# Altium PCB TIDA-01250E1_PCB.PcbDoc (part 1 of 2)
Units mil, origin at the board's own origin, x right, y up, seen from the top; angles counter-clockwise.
Board outline 2200 x 3000 mil, 2 copper layers (Top Layer, Bottom Layer), stack 62 mil thick; 78 components, 50 nets, 255 pads, 52 vias.
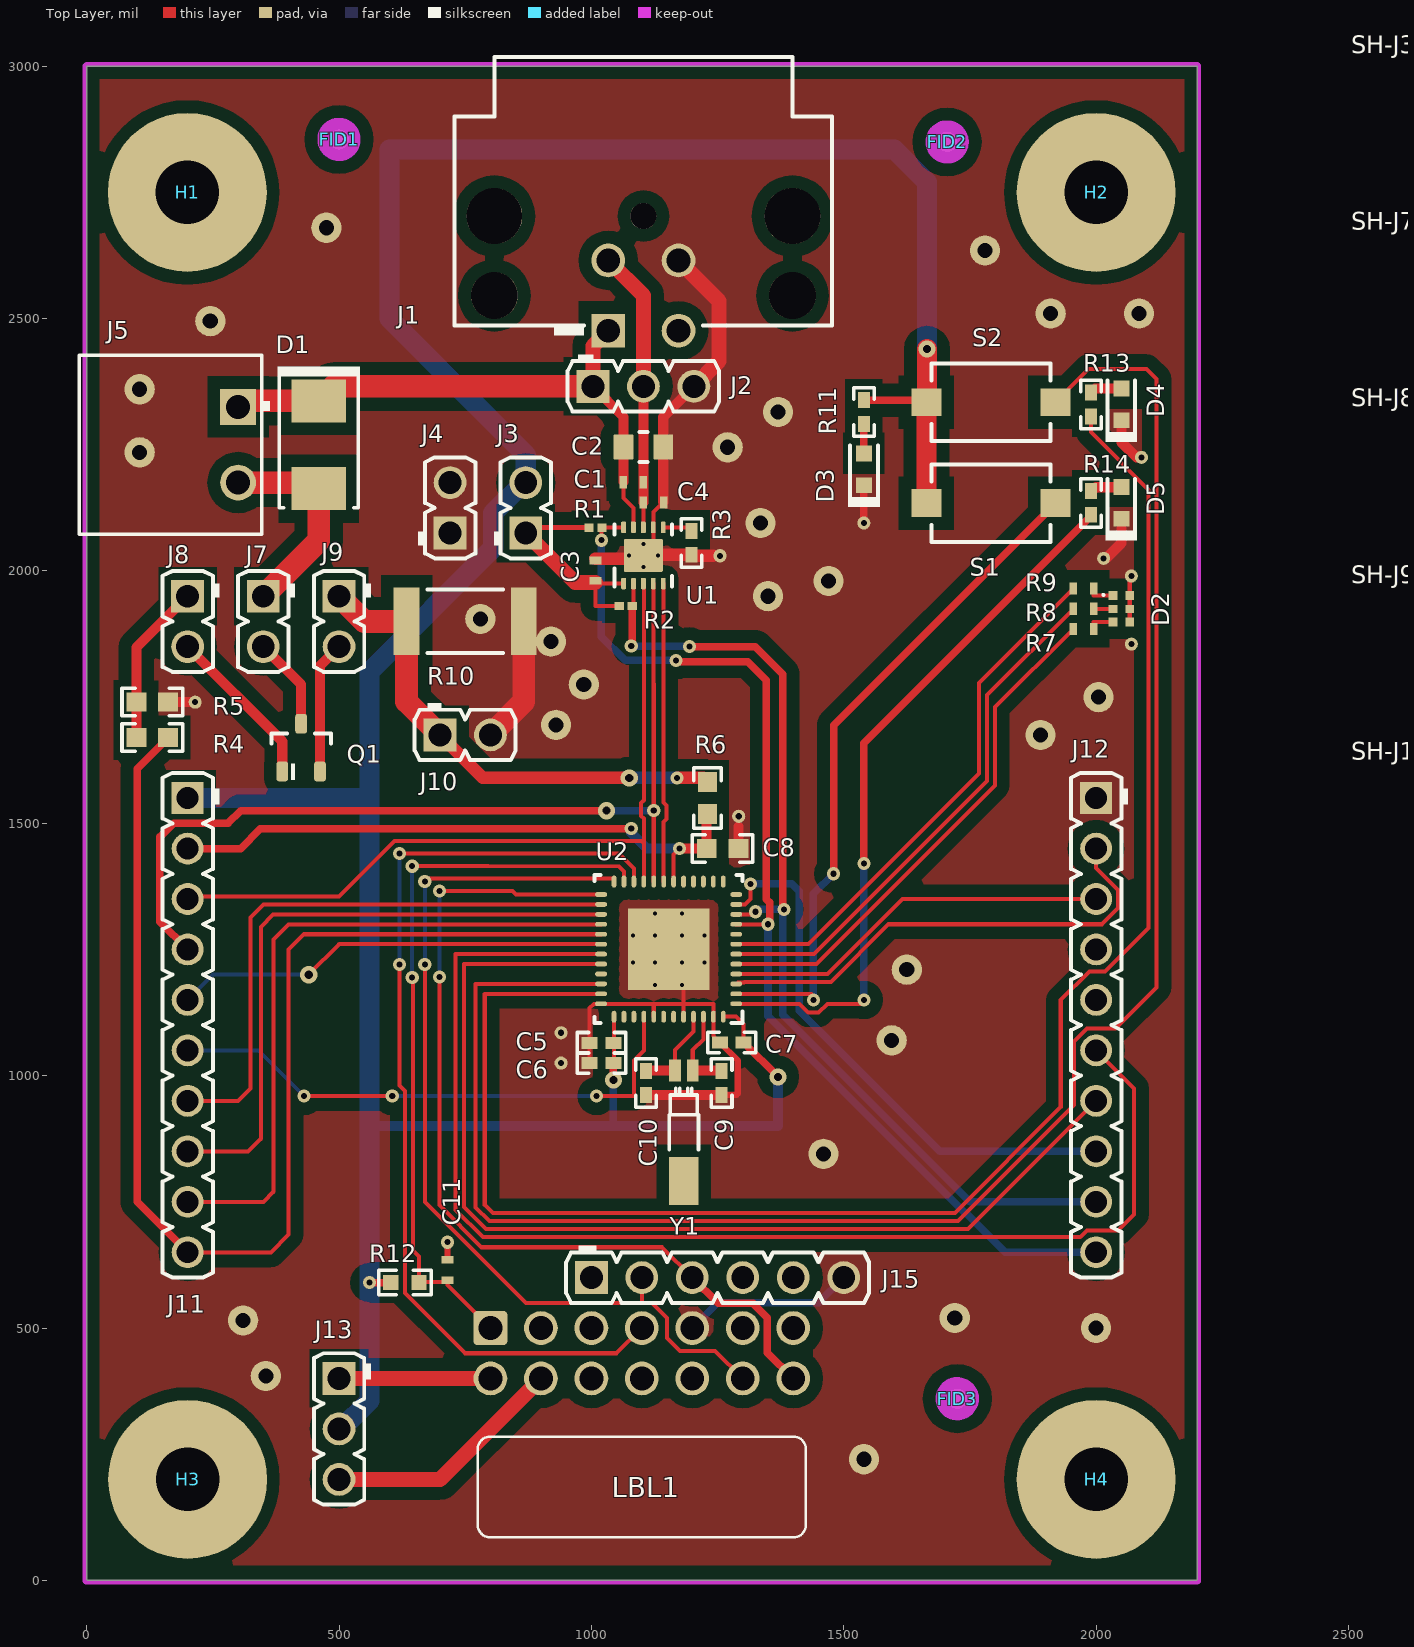
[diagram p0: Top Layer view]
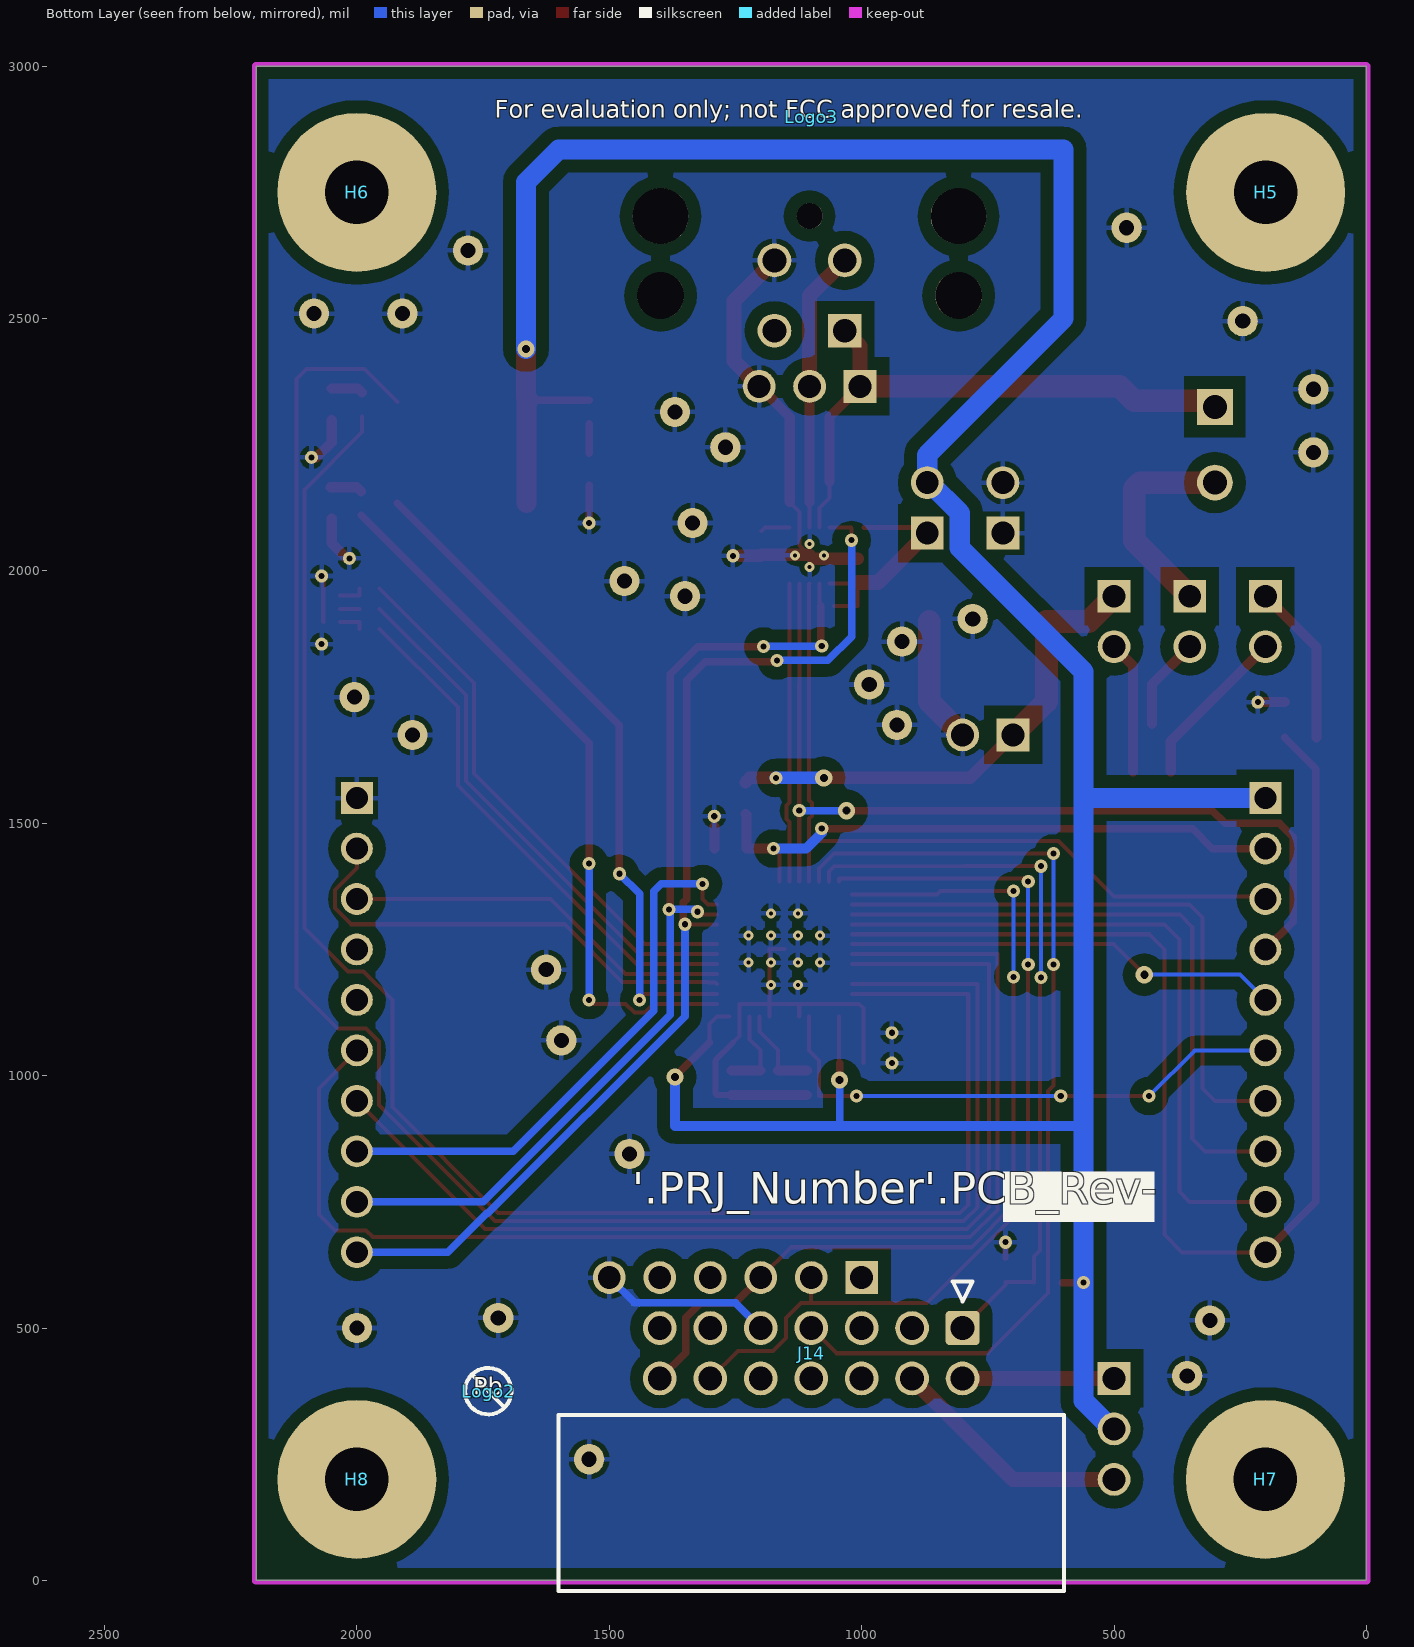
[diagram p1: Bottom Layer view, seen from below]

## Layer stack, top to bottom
Top Solder: solder mask 0.4, Solder Resist, Dk 3.5
Top Layer: signal copper 1.4
Dielectric1: core 59.2, FR-4, Dk 4.8
Bottom Layer: signal copper 1.4
Bottom Solder: solder mask 0.4, Solder Resist, Dk 3.5

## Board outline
0,0 2200,0 2200,3000 0,3000

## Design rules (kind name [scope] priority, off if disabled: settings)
AcuteAngle [All] p1: minimum=4.50000000000000E+0001 checktracksonly=FALSE
AssemblyTestPointUsage [All] p1: valid=2
BoardOutlineClearance BoardOutlineClearance_MountingHoles [OnCopper and InComponentClass('Mounting Holes')] p1: gap=40 ignorepadtopadclearanceinfootprint=FALSE
BoardOutlineClearance BoardOutlineClearance_Poly [OnCopper and IsPoly] p2: gap=25 ignorepadtopadclearanceinfootprint=FALSE
BoardOutlineClearance [OnCopper and Not InComponentClass('Logo') and not InComponentClass('FiducialMark') and not InRegion(1000,500,4000,800) and not InPoly] p3: gap=75 ignorepadtopadclearanceinfootprint=FALSE
Clearance Clearance_FiducialMark [IsKeepOut and InComponentClass('FiducialMark') vs IsPad and InComponentClass('FiducialMark')] p1: gap=0 ignorepadtopadclearanceinfootprint=FALSE
Clearance Clearance_Keepouts [((IsTrack Or IsArc) And Not InPoly) And IsFree and IsKeepOut vs ((IsTrack Or IsArc) And Not InPoly) And IsFree and IsKeepOut] p2: gap=0 ignorepadtopadclearanceinfootprint=FALSE
Clearance Clearance_Poly [InPolygon] p3: gap=25 ignorepadtopadclearanceinfootprint=FALSE except(0: Arc-Hole Track-Hole SMDPad-Hole THPad-Hole Via-Hole Fill-Hole Poly-Hole Region-Hole Text-Hole)
Clearance [All] p4: gap=7.87 ignorepadtopadclearanceinfootprint=FALSE except(0: Arc-Hole Track-Hole SMDPad-Hole THPad-Hole Via-Hole Fill-Hole Poly-Hole Region-Hole Text-Hole)
ComponentClearance ComponentClearance_MountingHoles_FiducialMarks [InComponentClass('Mounting Holes') vs InComponentClass('FiducialMark')] p1: gap=50 collisioncheckmode=3 verticalgap=10 showdistances=FALSE
ComponentClearance ComponentClearance_Shunt [InComponentClass('Header') vs InComponentClass('Shunt')] p2: gap=0 collisioncheckmode=3 verticalgap=0 showdistances=FALSE
ComponentClearance ComponentClearance_Logo [InComponentClass('Logo')] p3: gap=50 collisioncheckmode=3 verticalgap=10 showdistances=FALSE
ComponentClearance ComponentClearance_ScrewToNut [(HasFootprint('NY PMS 440 0025 PH')) vs (HasFootprint('Keystone_1902C'))] p4: gap=5 collisioncheckmode=3 verticalgap=10 showdistances=FALSE
ComponentClearance ComponentClearance_MountingHoles [InComponentClass('Mounting Holes')] p5: gap=100 collisioncheckmode=3 verticalgap=100000 showdistances=FALSE
ComponentClearance ComponentClearance_SmallPassives [HasFootprint('0201*') or HasFootprint('0402*') or HasFootprint('0508') or HasFootprint('0603*') or HasFootprint('0612') or HasFootprint('0805*') or HasFootprint('0815*') or HasFootprint('0830*') or HasFootprint('1206*') or HasFootprint('1210*') or HasFootprint('1808*') or HasFootprint('1812*') or HasFootprint('1825*') or HasFootprint('2010*') or HasFootprint('2220*') or HasFootprint('2225*') or HasFootprint('2512*') or HasFootprint('2728*') or HasFootprint('3518*') vs HasFootprint('0201*') or HasFootprint('0402*') or HasFootprint('0508') or HasFootprint('0603*') or HasFootprint('0612') or HasFootprint('0805*') or HasFootprint('0815*') or HasFootprint('0830*') or HasFootprint('1206*') or HasFootprint('1210*') or HasFootprint('1808*') or HasFootprint('1812*') or HasFootprint('1825*') or HasFootprint('2010*') or HasFootprint('2220*') or HasFootprint('2225*') or HasFootprint('2512*') or HasFootprint('2728*') or HasFootprint('3518*')] p6: gap=14.96 collisioncheckmode=3 verticalgap=10 showdistances=FALSE
ComponentClearance ComponentClearance_THtoSMT [IsThruComponent vs IsSMTComponent] p7: gap=40 collisioncheckmode=3 verticalgap=30 showdistances=FALSE
ComponentClearance ComponentClearance_THtoTH [IsThruComponent vs IsThruComponent] p8: gap=30 collisioncheckmode=3 verticalgap=30 showdistances=FALSE
ComponentClearance [All] p9: gap=30 collisioncheckmode=3 verticalgap=10 showdistances=FALSE
DiffPairsRouting [All] p1: maxlimit=100 minlimit=10 mostfreqgap=10 toplayer_minwidth=15 toplayer_maxwidth=15 toplayer_prefwidth=15 bottomlayer_minwidth=15 bottomlayer_maxwidth=15 bottomlayer_prefwidth=15 maxuncoupledlength=1000
FabricationTestPointUsage TestPointUsage [All] p1: valid=2 allowmultiple=FALSE
FabricationTestpoint Testpoint [All] p1: side=3 testpointundercomponent=TRUE minsize=40 maxsize=100 preferedsize=60 minholesize=0 maxholesize=40 preferedholesize=32 testpointgrid=1 allowsidetop=TRUE allowsidebottom=TRUE usegrid=TRUE gridtolerance=0.01
FanoutControl Fanout_LCC [IsLCC] p1: bgadir=Out bgaviamode=Centered fanoutstyle=Auto fanoutdirection=Alternating viagrid=1 // Fanout_LCC (Default Rule)
FanoutControl Fanout_BGA [IsBGA] p2: bgadir=Out bgaviamode=Centered fanoutstyle=Auto fanoutdirection=Alternating viagrid=1 // Fanout_BGA (Default Rule)
FanoutControl Fanout_Default [All] p4: bgadir=Out bgaviamode=Centered fanoutstyle=Auto fanoutdirection=Alternating viagrid=1 // Fanout_Default (Default Rule)
FanoutControl Fanout_Small [(CompPinCount < 5)] p5: bgadir=Out bgaviamode=Centered fanoutstyle=Auto fanoutdirection=OutThenIn viagrid=1 // Fanout_Small (Default Rule)
HoleSize [All] p1: absolutevalues=TRUE maxlimit=251 minlimit=7.87 maxpercent=80.000 minpercent=20.000
MinimumAnnularRing MinimumAnnularRing_ThermalPadVias [IsVia and InAnyComponent] p1: minimumring=5.91
MinimumAnnularRing [All] p2: minimumring=6.9
MinimumSolderMaskSliver MinimumSolderMaskSliver_Logo [InComponentClass('Logo') vs InComponentClass('Logo')] p1: minsoldermaskwidth=0.7
MinimumSolderMaskSliver [All] p2: minsoldermaskwidth=3.94
PlaneConnect [All] p1: planeconnectstyle=Relief reliefexpansion=10 reliefentries=4 reliefconductorwidth=10 reliefairgap=10
PolygonConnect PolygonConnect_1 [All vs IsNamedPolygon('TOP_LAYER_GND_P002')] p1: connectstyle=Direct reliefconductorwidth=10 reliefentries=4 polygonreliefangle="90 Angle" airgapwidth=10
PolygonConnect [All] p2: connectstyle=Relief reliefconductorwidth=10 reliefentries=4 polygonreliefangle="90 Angle" airgapwidth=10
RoutingVias ThermalPadVias [IsVia and InAnyComponent] p1: holewidth=7.87 width=19.68 viastyle="Through Hole" minholewidth=7.87 minwidth=19.68 maxholewidth=12.99 maxwidth=23.62
RoutingVias [All] p2: holewidth=16 width=34 viastyle="Through Hole" minholewidth=7.87 minwidth=26 maxholewidth=40 maxwidth=65
SilkToBoardRegionClearance [Not ((IsComment or IsDesignator) And (Hide <> 'False')) and not InRegion(1000,500,4000,800)] p1:
SilkToSilkClearance SilkToSilkClearance_Pb-FreeLogo [(HasFootprint('Pb-Free_Overlay_Medium') OR HasFootprint('Pb-Free_Overlay_Small')) vs (HasFootprint('Pb-Free_Overlay_Medium') OR HasFootprint('Pb-Free_Overlay_Small'))] p1: silktosilkclearance=0
SilkToSilkClearance [All] p2: silktosilkclearance=4
SilkToSolderMaskClearance SilkToComponentPadClearance [(IsPad or IsFill or IsRegion) and InAnycomponent] p1: minsilkscreentomaskgap=5 clearancetoexposedcopper=TRUE
SilkToSolderMaskClearance "Silk to Solder Mask Opening" [All] p2: minsilkscreentomaskgap=4 clearancetoexposedcopper=FALSE
SolderMaskExpansion [All] p1: expansion=1.97
Width [All] p1: maxlimit=100 minlimit=6 preferedwidth=10 checkconnectedcopper=TRUE
15 further rules are at their usual default settings.

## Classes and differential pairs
component class TIDA-01250E1_Schematic: C1 C2 C3 C4 C5 C6 C7 C8 C9 C10 C11 D1 D2 D3 D4 D5 J1 J2 J3 J4 J5 J7 J8 J9 J10 J11 J12 J13 J14 J15 Q1 R1 R2 R3 R4 R5 R6 R7 R8 R9 R10 R11 R12 R13 R14 S1 S2 SH-J3 SH-J7 SH-J8 SH-J9 SH-J13 U1 U2 Y1
component class Header: J2 J3 J4 J7 J8 J9 J10 J11 J12 J13 J15
component class "Mounting Holes": H1 H2 H3 H4
component class TIDA-01250E1_EVM_Hardware: FID1 FID2 FID3 H1 H2 H3 H4 H5 H6 H7 H8 LBL1 Logo2 Logo3 ZZ1 ZZ2 ZZ3 ZZ4 ZZ5 ZZ6 ZZ7 ZZ8 ZZ9
component class FiducialMark: FID1 FID2 FID3
component class AssemblyNote: ZZ1 ZZ2 ZZ3 ZZ4 ZZ5 ZZ6 ZZ7 ZZ8 ZZ9
component class Label: LBL1

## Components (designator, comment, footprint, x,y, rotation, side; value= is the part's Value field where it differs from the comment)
C1 "GRM1555C1H151JA01D" 0402S 1083.15,2175.67 r0 top value=150pF
C2 "CGA4J3X7S2A105K125AB" 0805_HV1 1103.15,2245.67 r0 top value=1uF
C3 "GRM155R61A105KE15D" 0402S 1008.15,2000.67 r90 top value=1uF
C4 "GRM1555C1H151JA01D" 0402S 1123.15,2135.67 r0 top value=150pF
C5 "GRM155R71C104JA88D" 0402 1020,1065 r180 top value=0.1uF
C6 "GRM155R61A105KE15D" 0402 1020,1025 r180 top value=1uF
C7 "GRM155R71C104JA88D" 0402 1278.15,1065.67 r180 top value=0.1uF
C8 "GRM1885C1H101JA01D" 0603 1260,1450 r0 top value=100pF
C9 "GRM1555C1H100RA01D" 0402 1258.15,985.67 r270 top value=10pF
C10 "GRM1555C1H100RA01D" 0402 1108.15,985.67 r270 top value=10pF
C11 "885012205061" 0402S 715,615 r90 top value=1000pF
D1 "MURS160-13-F" SMB 460,2250 r270 top value=600V
D2 "SMLP36RGB2W3" PicoLED_RGB_150x100 2050,1925 r0 top value=Rgb
D3 "150060VS75000" WL-SMCW_GREEN 1540,2201.4 r90 top value=Green
D4 "150060VS75000" WL-SMCW_GREEN 2050,2330 r90 top value=Green
D5 "150060VS75000" WL-SMCW_GREEN 2050,2135 r90 top value=Green
FID1 "Fiducial" Fiducial10-20 500,2855 r0 top
FID2 "Fiducial" Fiducial10-20 1705,2850 r0 top
FID3 "Fiducial" Fiducial10-20 1725,360 r0 top
H1 "NY PMS 440 0025 PH" "NY PMS 440 0025 PH" 199.47,2750 r0 top locked
H2 "NY PMS 440 0025 PH" "NY PMS 440 0025 PH" 2000,2750 r0 top locked
H3 "NY PMS 440 0025 PH" "NY PMS 440 0025 PH" 200,200 r0 top locked
H4 "NY PMS 440 0025 PH" "NY PMS 440 0025 PH" 2000,200 r0 top locked
H5 "1902C" Keystone_1902C 199.47,2750 r180 bottom locked
H6 "1902C" Keystone_1902C 2000,2750 r180 bottom locked
H7 "1902C" Keystone_1902C 200,200 r180 bottom locked
H8 "1902C" Keystone_1902C 2000,200 r180 bottom locked
J1 "PartNumber" Conec_43-01205 1103.15,2545.67 r90 top
J2 "61300311121" WURTH_61300311121 1103.16,2365.68 r0 top
J3 "61300211121" WURTH_61300211121 870,2125 r90 top
J4 "61300211121" WURTH_61300211121 720,2125 r90 top
J5 "1803277" PhoenixContact_1803277 300,2250 r270 top
J7 "61300211121" WURTH_61300211121 350,1900 r270 top
J8 "61300211121" WURTH_61300211121 200,1900 r270 top
J9 "61300211121" WURTH_61300211121 500,1900 r270 top
J10 "61300211121" WURTH_61300211121 750,1675 r0 top
J11 "61301011121" Wurth_61301011121 200,1100 r270 top
J12 "61301011121" Wurth_61301011121 2000,1100 r270 top
J13 "61300311121" WURTH_61300311121 500,300 r270 top
J14 "612 014 217 21" WURTH_612_014_217_21_Correct 1100,450 r270 bottom
J15 "61300611121" WURTH_61300611121 1250,600 r0 top
LBL1 "THT-14-423-10" Label_650x200 1100,185 r0 top
Logo2 "Pb-Free Symbol" Pb-Free_Overlay_Small 1740,375 r180 bottom
Logo3 "FCC disclaimer" FCC_disclaimer 1100,2900 r180 bottom
Q1 "DMN61D8L-7" SOT-23 425,1650 r90 top value=60V
R1 "CRCW020110K0FKED" 0201 1008.15,2085.67 r180 top value=10.0k
R2 "CRCW020110K0FKED" 0201 1068.15,1930.67 r180 top value=10.0k
R3 "CRCW04020000Z0ED" 0402 1198.15,2055.67 r270 top value=0
R4 "CRCW06030000Z0EA" 0603 130,1670 r180 top value=0
R5 "CRCW0603100KFKEA" 0603 130,1740 r180 top value=100k
R6 "CRCW06031K00FKEA" 0603 1230,1550 r90 top value=1.00k
R7 "CRCW0402140RFKED" 0402S 1975,1885 r0 top value=140
R8 "CRCW0402140RFKED" 0402S 1975,1925 r0 top value=140
R9 "CRCW0402499RFKED" 0402S 1975,1965 r0 top value=499
R10 "CRCW25121R00FNEG" 2512 750,1900 r180 top value=1.00
R11 "CRCW040268R1FKED" 0402 1540,2315 r270 top value=68.1
R12 "CRCW060347K5FKEA" 0603_HV 630.41,590 r180 top value=47.5k
R13 "CRCW040268R1FKED" 0402 1990,2330 r90 top value=68.1
R14 "CRCW040268R1FKED" 0402 1990,2135 r90 top value=68.1
S1 "434121025816" SW_434121025816 1791.85,2134.33 r180 top
S2 "434121025816" SW_434121025816 1791.85,2334.33 r180 top
SH-J3 "60900213421" Wurth_60900213421 2550,2900 r90 top
SH-J7 "60900213421" Wurth_60900213421 2550,2550 r90 top
SH-J8 "60900213421" Wurth_60900213421 2550,2200 r90 top
SH-J9 "60900213421" Wurth_60900213421 2550,1850 r90 top
SH-J13 "60900213421" Wurth_60900213421 2550,1500 r90 top
U1 "TIOL111" TIOL111 1103.15,2030.67 r90 top
U2 "MSP430FR5969IRGZR" RGZ0048B 1153.15,1250.67 r180 top
Y1 "MS3V-T1R 32.768KHZ 7.0 PF" XTAL_MS3V-T1R 1183.15,900.67 r270 top
ZZ1 "This Assembly Note is for PCB labels only" AssemblyNoteLabel 185,3938 r0 top
ZZ2 "This Assembly Note will show in the PcbDoc and associated outputs" AssemblyNote 185,3829.11 r0 top
ZZ3 "This Assembly Note will show in the PcbDoc and associated outputs" AssemblyNote 185,3740.56 r0 top
ZZ4 "This Assembly Note will show in the PcbDoc and associated outputs" AssemblyNote 185,3652 r0 top
ZZ5 "This Assembly Note will show in the PcbDoc and associated outputs" AssemblyNote 2900,2950 r0 top
ZZ6 "This Assembly Note will show in the PcbDoc and associated outputs" AssemblyNote 2900,2600 r0 top
ZZ7 "This Assembly Note will show in the PcbDoc and associated outputs" AssemblyNote 2900,2250 r0 top
ZZ8 "This Assembly Note will show in the PcbDoc and associated outputs" AssemblyNote 2900,1900 r0 top
ZZ9 "This Assembly Note will show in the PcbDoc and associated outputs" AssemblyNote 2900,1550 r0 top

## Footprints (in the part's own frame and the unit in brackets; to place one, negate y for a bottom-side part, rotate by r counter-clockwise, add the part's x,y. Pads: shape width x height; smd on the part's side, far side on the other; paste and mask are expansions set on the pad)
0201 [mm] "Data from Kemet datasheet CC101_COM dated 7/28/11"
  rect 0.46x0.42 smd mask+0.048: 1(-0.33,0) 2(0.33,0)
  body extent -0.31,-0.16 0.31,0.16, height 0.26
0402 [mm] "0402 from SM-752 data"
  rect 0.8x0.6 smd: 1(-0.6,0) 2(0.6,0)
  silkscreen extent -1.22,-0.52 1.22,0.52, body extent -0.55,-0.3 0.55,0.3, height 0.6
0402S [mil] "Based on C0402S footprint from PADS legacy"
  rect 15x24 smd: 1(-20,0) 2(20,0)
  body extent -22,-12 22,12, height 24
0603 [mm] "0603 from SM-752 data"
  rect 1x0.95 smd: 1(-0.8,0) 2(0.8,0)
  silkscreen extent -1.52,-0.69 1.52,0.69, body extent -0.87,-0.47 0.87,0.47, height 1
0603_HV [mil] "Ernesto recommended land pattern.  26 mil between pads."
  rect 30x30 smd: 1(-28,0) 2(28,0)
  silkscreen extent -52,-24 52,24, body extent -34,-19 34,19, height 39
0805_HV1 [mm] "Custom footprint based on analyzing multiple manufacturer recommendations"
  rrect10% 1x1.25 smd: 1(-1,0) 2(1,0)
  silkscreen extent -0.2,-0.75 0.2,0.75, body extent -1.1,-0.72 1.1,0.73, height 1.45
2512 [mm] "Chip Resistor, Body 6.3x3.2mm, IPC Medium Density"
  rect 1.3x3.4 smd: 1(-2.95,0) 2(2.95,0)
  silkscreen extent -1.9,-1.6 1.9,1.6, body extent -3.22,-1.67 3.22,1.67, height 0.71
AssemblyNote [mil] "Assembly Note"
AssemblyNoteLabel [mil] "Assembly Note for PCB Labels"
Conec_43-01205 [mm] "M12 Socket, Backmounting, 4Pos, R/A, TH"
  rect 1.7x1.7 hole 1.2: 1(-1.768,1.768)
  round 1.7 hole 1.2: 2(-1.768,-1.768) 3(1.768,-1.768) 4(1.768,1.768)
  round 2.35 hole 2.35 unplated mask+0: 5(0,7.5) 6(0,-7.5)
  round 2.8 hole 2.8 unplated mask+0: 7(4,-7.5) 8(4,7.5)
  round 1.3 hole 1.3 unplated mask+0: 9(4,0)
  silkscreen extent -2,-9.5 12,9.5, body extent -2.15,-9.5 25,9.5, height 17
FCC_disclaimer [mil]
Fiducial10-20 [mm]
  round 1 smd mask+0.5: 1(0,0)
  Top Layer keep-out circle w1.178: c0,0 r0.5
Keystone_1902C [mil] "Hex Standoff, 4-40 threaded, nylon"
  round 1 on Mech4: 0(0,0)
  body extent -145,-126 146,126, height 501
Label_650x200 [mil] "Thermal Transfer Label"
  round 1 on Mech13: 0(0,0)
  silkscreen extent -325,-100 325,100, body extent -325,-100 325,100, height 1
"NY PMS 440 0025 PH" [mm] "4-40 nylon screw and mounting hole"
  round 8 hole 3.2: 1(0,0)
  body extent -3.3,-3.3 3.3,3.3, height 2.69
Pb-Free_Overlay_Small [mil]
  silkscreen extent -46,-46 46,46
PhoenixContact_1803277 [mm] "Phoenix Contact"
  rect 1.8x1.8 hole 1.2: 1(-1.905,0)
  round 1.8 hole 1.2: 2(1.905,0)
  silkscreen extent -4.5,-8 4.51,1.6, body extent -4.5,-8 4.51,1.3, height 7.26
PicoLED_RGB_150x100 [mm] "SMD, 6-Leads, Body 1.5x1mm"
  rect 0.45x0.45 smd: 1(-0.425,0.675) 3(-0.425,-0.675) 4(0.425,-0.675) 6(0.425,0.675)
  rect 0.45x0.4 smd: 2(-0.425,0) 5(0.425,0)
  silkscreen extent -0.95,0.65 -0.85,0.75, body extent -0.5,-0.75 0.5,0.75, height 0.25
RGZ0048B [mm] "QFN, 48-Leads, Body 7x7mm, Pitch 0.5mm, Thermal Pad 5.15x5.15mm, TI Recommended"
  oval 0.6x0.24 smd: 1(-3.4,2.75) 2(-3.4,2.25) 3(-3.4,1.75) 4(-3.4,1.25) 5(-3.4,0.75) 6(-3.4,0.25) 7(-3.4,-0.25) 8(-3.4,-0.75) 9(-3.4,-1.25) 10(-3.4,-1.75) 11(-3.4,-2.25) 12(-3.4,-2.75) 25(3.4,-2.75) 26(3.4,-2.25) 27(3.4,-1.75) 28(3.4,-1.25) 29(3.4,-0.75) 30(3.4,-0.25) 31(3.4,0.25) 32(3.4,0.75) 33(3.4,1.25) 34(3.4,1.75) 35(3.4,2.25) 36(3.4,2.75)
  oval 0.24x0.6 smd: 13(-2.75,-3.4) 14(-2.25,-3.4) 15(-1.75,-3.4) 16(-1.25,-3.4) 17(-0.75,-3.4) 18(-0.25,-3.4) 19(0.25,-3.4) 20(0.75,-3.4) 21(1.25,-3.4) 22(1.75,-3.4) 23(2.25,-3.4) 24(2.75,-3.4) 37(2.75,3.4) 38(2.25,3.4) 39(1.75,3.4) 40(1.25,3.4) 41(0.75,3.4) 42(0.25,3.4) 43(-0.25,3.4) 44(-0.75,3.4) 45(-1.25,3.4) 46(-1.75,3.4) 47(-2.25,3.4) 48(-2.75,3.4)
  rect 4.1x4.1 smd paste-2.575: 49(0,0)
  silkscreen extent -3.72,-3.72 3.72,3.72, body extent -3.57,-3.58 3.58,3.57, height 1.01
SMB [mil] "Molded Diode, 2-Leads, Body 5.4x3.6mm, IPC Medium Density, based on OnSemi component dimensions"
  rect 85x107.99 smd: 1(-87.01,0) 2(87.01,0)
  silkscreen extent -155,-82 125,82, body extent -106,-71 106,71, height 91
SOT-23 [mm] "SOT23, 3-Leads, Body 2.9x1.3mm, Pitch 0.95mm, Lead Span 2.5mm, IPC Medium Density"
  rrect50% 1x0.6 smd: 1(-1.2,0.95) 2(-1.2,-0.95) 3(1.2,0)
  silkscreen extent -1.62,-1.5 0.7,1.5, body extent -1.16,-1.45 1.21,1.45, height 1
SW_434121025816 [mm] "SMD, 2-Leads, Body 6x3.9mm, Pitch 6.5mm"
  rect 1.5x1.4 smd: 1(-3.25,0) 2(3.25,0)
  silkscreen extent -3,-1.95 3,1.95, body extent -3.65,-1.95 3.65,1.95, height 2.5
TIOL111 [mm] "SON, 10-Leads, Body 2.5x3mm, Pitch 0.5mm, Thermal Pad 1.95x1.65mm"
  rrect40% 0.575x0.24 smd: 1(-1.412,1) 2(-1.412,0.5) 3(-1.412,0) 4(-1.412,-0.5) 5(-1.412,-1) 6(1.412,-1) 7(1.412,-0.5) 8(1.412,0) 9(1.412,0.5) 10(1.412,1)
  rrect6% 1.65x1.95 smd paste-2: 11(0,0)
  silkscreen extent -1.55,-1.45 1.55,1.45, body extent -1.55,-1.3 1.55,1.3, height 1.02
WL-SMCW_GREEN [mm] "WURTH"
  rect 0.8x0.8 smd: 1(-0.8,0) 2(0.8,0)
  silkscreen extent -1.9,-0.8 1.2,0.8, body extent -0.85,-0.45 0.85,0.45, height 0.8
WURTH_612_014_217_21_Correct [mm] "Header, 2.54 mm, 7x2, R/A, TH"
  rrect20% 1.7x1.7 hole 1.2: 1(-1.27,7.62)
  round 1.7 hole 1.2: 2(1.27,7.62) 3(-1.27,5.08) 4(1.27,5.08) 5(-1.27,2.54) 6(1.27,2.54) 7(-1.27,0) 8(1.27,0) 9(-1.27,-2.54) 10(1.27,-2.54) 11(-1.27,-5.08) 12(1.27,-5.08) 13(-1.27,-7.62) 14(1.27,-7.62)
  silkscreen extent -3.6,-12.72 11.96,12.72, body extent -1.59,-12.72 11.96,12.72, height 9.1
Wurth_60900213421 [mil] "Shunt, 2.54mm, Black"
  round 1 on Mech3: 0(0,0)
  body extent -98,-48 98,48, height 236
WURTH_61300211121 [mm] "Header, 2.54mm, 2x1, TH"
  rect 1.65x1.65 hole 1.15: 1(-1.27,0)
  round 1.65 hole 1.15: 2(1.27,0)
  silkscreen extent -2.54,-1.27 2.54,1.6, body extent -2.54,-1.27 2.54,1.27, height 8.54
WURTH_61300311121 [mm] "Header, 2.54mm, 3x1, TH"
  rect 1.65x1.65 hole 1.15: 1(-2.54,0)
  round 1.65 hole 1.15: 2(0,0) 3(2.54,0)
  silkscreen extent -3.81,-1.27 3.81,1.6, body extent -3.81,-1.27 3.81,1.27, height 8.54
WURTH_61300611121 [mm] "Header, 2.54mm, 6x1, TH"
  rect 1.65x1.65 hole 1.15: 1(-6.35,0)
  round 1.65 hole 1.15: 2(-3.81,0) 3(-1.27,0) 4(1.27,0) 5(3.81,0) 6(6.35,0)
  silkscreen extent -7.62,-1.27 7.62,1.6, body extent -7.62,-1.27 7.62,1.27, height 8.54
Wurth_61301011121 [mm] "Header, 2.54mm, 10x1, TH"
  rect 1.6x1.6 hole 1.1: 1(-11.43,0)
  round 1.6 hole 1.1: 2(-8.89,0) 3(-6.35,0) 4(-3.81,0) 5(-1.27,0) 6(1.27,0) 7(3.81,0) 8(6.35,0) 9(8.89,0) 10(11.43,0)
  silkscreen extent -12.7,-1.27 12.7,1.6, body extent -12.7,-1.27 12.7,1.27, height 8.54
XTAL_MS3V-T1R [mm] "Micro Crystal Switzerland recommended land pattern"
  rect 1.1x0.6 smd: 1(-2.775,0.45) 2(-2.775,-0.45)
  rect 2.4x1.5 smd: 3(2.775,0)
  silkscreen extent -1.9,-0.74 1.2,0.74, body extent -3.05,-0.74 3.65,0.74, height 1.42

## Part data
C1 C4: library part CMP-0006421-1, "CAP, CERM, 150 pF, 50 V, +/- 5%, C0G/NP0, 0402", Cap_Case=0402, Manufacturer=MuRata, Supplier Part Number 1=490-3229-1-ND, TempCo=C0G/NP0, Tolerance_%=5%, Value1=Unknown, Value2=50V, ValueDisplayed=150pF
C2: library part CMP-0007980-2, "CAP, CERM, 1 uF, 100 V, +/- 10%, X7S, AEC-Q200 Grade 1, 0805", Cap_Case=0805, Manufacturer=TDK, Supplier Part Number 1=445-6974-1-ND, TempCo=X7S, Tolerance_%=10%, Value1="0.008255 ohm", Value2=100V, ValueDisplayed=1uF
C3 C6: library part CMP-0006563-2, "CAP, CERM, 1 uF, 10 V, +/- 10%, X5R, 0402", Cap_Case=0402, Manufacturer=MuRata, Supplier Part Number 1=490-3890-1-ND, TempCo=X5R, Tolerance_%=10%, Value1=Unknown, Value2=10V, ValueDisplayed=1uF
C5 C7: library part CMP-0006640-2, "CAP, CERM, 0.1 uF, 16 V, +/- 5%, X7R, 0402", Cap_Case=0402, Manufacturer=MuRata, Supplier Part Number 1=490-6327-1-ND, TempCo=X7R, Tolerance_%=5%, Value1=Unknown, Value2=16V, ValueDisplayed=0.1uF
C8: library part CMP-0007171-1, "CAP, CERM, 100 pF, 50 V, +/- 5%, C0G/NP0, 0603", Cap_Case=0603, Manufacturer=MuRata, Supplier Part Number 1=490-1427-1-ND, TempCo=C0G/NP0, Tolerance_%=5%, Value1=Unknown, Value2=50V, ValueDisplayed=100pF
C9 C10: library part CMP-0006409-1, "CAP, CERM, 10 pF, 50 V, +/- 4%, C0G/NP0, 0402", Cap_Case=0402, Manufacturer=MuRata, Supplier Part Number 1=490-11374-1-ND, TempCo=C0G/NP0, Tolerance_%=4%, Value1=Unknown, Value2=50V, ValueDisplayed=10pF
C11: library part CMP-0006231-2, "CAP, CERM, 1000 pF, 50 V, +/- 10%, X7R, 0402", Cap_Case=0402, Manufacturer="Wurth Elektronik", Supplier Part Number 1=732-7556-1-ND, TempCo=X7R, Tolerance_%=10%, Value1=Unknown, Value2=50V, ValueDisplayed=1000pF
D1: library part CMP-0029028-1, "Diode, Ultrafast, 600 V, 1 A, SMB", Manufacturer="Diodes Inc.", Supplier Part Number 1=MURS160-FDICT-ND, Value1=1A, Value2=1.25V
D2: library part CMP-0002932-2, "LED, Rgb, SMD", Color=RGB, Manufacturer=Rohm, Supplier Part Number 1=846-1097-1-ND, Value1=W, Value2=3.1V
D3 D4 D5: library part CMP-0002894-1, "LED, Green, SMD", Color=green, Manufacturer="Wurth Elektronik", Supplier Part Number 1=732-4980-1-ND, Value1=W, Value2=2V
FID1 FID2 FID3: "Fiducial mark.  There is nothing to buy or mount.", Manufacturer=N/A
H1 H2 H3 H4: library part CMP-0003617-1, "Machine Screw, Round, #4-40 x 1/4, Nylon, Philips panhead", Manufacturer="B&F Fastener Supply", Supplier Part Number 1=H542-ND
H5 H6 H7 H8: library part CMP-0003610-1, "Standoff, Hex, 0.5\"L #4-40 Nylon", Manufacturer=Keystone, Supplier Part Number 1=36-1902C-ND
J1: library part 43-01205, "M12 Socket, Backmounting, 4Pos, Gold, R/A, TH"
J2 J13: library part CMP-0054796-1, "Header, 2.54 mm, 3x1, Gold, TH", Manufacturer="Wurth Elektronik", Supplier Part Number 1=732-5316-ND
J3 J4 J7 J8 J9 J10: library part CMP-0054794-1, "Header, 2.54 mm, 2x1, Gold, TH", Manufacturer="Wurth Elektronik", Supplier Part Number 1=732-5315-ND
J5: library part CMP-0055494-1, "Terminal Block, 2x1, 3.81mm, R/A, TH", Manufacturer="Phoenix Contact", Supplier Part Number 1=277-1206-ND
J11 J12: library part CMP-0054804-1, "Header, 2.54mm, 10x1, Gold, TH", Color=Black, Manufacturer="Wurth Elektronik", Supplier Part Number 1=732-2670-ND
J14: library part CMP-0054781-1, "Header (Shrouded), 2.54 mm, 7x2, Gold, R/A, TH", Manufacturer="Wurth Elektronik", Supplier Part Number 1=732-5407-ND
J15: library part CMP-0054801-1, "Header, 2.54 mm, 6x1, Gold, TH", Manufacturer="Wurth Elektronik", Supplier Part Number 1=732-5319-ND
LBL1: library part CMP-0003625-1, "Thermal Transfer Printable Labels, 0.650\" W x 0.200\" H - 10,000 per roll", Manufacturer=Brady, Supplier Part Number 1=97C5133
Logo2: library part Pb-Free
Logo3: library part FCC_disclaimer, "FCC_disclaimer"
Q1: library part CMP-0000830-1, "MOSFET, N-CH, 60 V, 0.47 A, AEC-Q101, SOT-23", Alternate Manufacturer=None, Manufacturer="Diodes Inc.", Supplier Part Number 1=DMN61D8L-7DICT-ND, Value2="0.74 nC"
R1 R2: library part CMP-0027262-1, "RES, 10.0 k, 1%, 0.05 W, 0201", Manufacturer=Vishay-Dale, Power_W=50mW, Supplier Part Number 1=541-10.0KAABCT-ND, TempCo="100 ppm/C", Tolerance_%=1%, Value2=0.05W, Value_Code=10k0, ValueDisplayed=10.0k
R3: library part CMP-0026822-1, "RES, 0, 5%, 0.063 W, 0402", Manufacturer=Vishay-Dale, Power_W=63mW, Supplier Part Number 1=541-0.0JCT-ND, TempCo="200 ppm/C", Tolerance_%=5%, Value2=0.063W, Value_Code=0000, ValueDisplayed=0
R4: library part CMP-0025697-1, "RES, 0, 5%, 0.1 W, 0603", Manufacturer=Vishay-Dale, Power_W=100mW, Supplier Part Number 1=541-0.0GCT-ND, TempCo="200 ppm/C", Tolerance_%=5%, Value2=0.1W, Value_Code=0000, ValueDisplayed=0
R5: library part CMP-0021990-1, "RES, 100 k, 1%, 0.1 W, 0603", Manufacturer=Vishay-Dale, Power_W=100mW, Supplier Part Number 1=541-100KHCT-ND, TempCo="100 ppm/C", Tolerance_%=1%, Value2=0.1W, Value_Code=100k
R6: library part CMP-0022109-2, "RES, 1.00 k, 1%, 0.1 W, 0603", Manufacturer=Vishay-Dale, Power_W=100mW, Supplier Part Number 1=541-1.00KHCT-ND, TempCo="100 ppm/C", Tolerance_%=1%, Value2=0.1W, Value_Code=1k00, ValueDisplayed=1.00k
R7 R8: library part CMP-0026010-2, "RES, 140, 1%, 0.063 W, 0402", Manufacturer=Vishay-Dale, Power_W=63mW, Supplier Part Number 1=541-140LCT-ND, TempCo="100 ppm/C", Tolerance_%=1%, Value2=0.063W, Value_Code=140R, ValueDisplayed=140
R9: library part CMP-0026402-1, "RES, 499, 1%, 0.063 W, 0402", Manufacturer=Vishay-Dale, Power_W=63mW, Supplier Part Number 1=541-499LCT-ND, TempCo="100 ppm/C", Tolerance_%=1%, Value2=0.063W, Value_Code=499R, ValueDisplayed=499
R10: library part CMP-0015520-1, "RES, 1.00, 1%, 1 W, AEC-Q200 Grade 0, 2512", Manufacturer=Vishay-Dale, Power_W=1W, Supplier Part Number 1=541-1.00AFCT-ND, TempCo="200 ppm/C", Tolerance_%=1%, Value_Code=1R00, ValueDisplayed=1.00
R11 R13 R14: library part CMP-0026507-1, "RES, 68.1, 1%, 0.063 W, 0402", Manufacturer=Vishay-Dale, Power_W=63mW, Supplier Part Number 1=541-68.1LCT-ND, TempCo="100 ppm/C", Tolerance_%=1%, Value2=0.063W, Value_Code=68R1, ValueDisplayed=68.1
R12: library part CMP-0022439-1, "RES, 47.5 k, 1%, 0.1 W, 0603", Manufacturer=Vishay-Dale, Power_W=100mW, Supplier Part Number 1=541-47.5KHCT-ND, TempCo="100 ppm/C", Tolerance_%=1%, Value2=0.1W, Value_Code=47k5, ValueDisplayed=47.5k
S1 S2: library part CMP-0002196-1, "Switch, Tactile, SPST, 12 V, SMD", CurrentRating_mA=50A, Manufacturer="Wurth Elektronik", Supplier Part Number 1=31T8978
SH-J3 SH-J7 SH-J8 SH-J9 SH-J13: library part CMP-0003761-1, "Shunt, 2.54mm, Gold, Black", Manufacturer="Wurth Elektronik", Supplier Part Number 1=732-2678-ND
U1: library part CMP-0014126-1, "IO-Link Device Transceiver with Integrated Surge Protection, TIOL111 (WSON-10)", Alternate Manufacturer="Texas Instruments"
U2: library part CMP-0066503-1, "MSP430FR5969 16 MHz Ultra-Low-Power Microcontroller featuring 64 KB FRAM, 2 KB SRAM, 40 IO, RGZ0048B (VQFN-48)", Alternate Manufacturer="Texas Instruments", Alternate PartNumber=MSP430FR5969IRGZT
Y1: library part CMP-0004695-1, "Crystal, 32.768 KHz, 7pF, SMD", Frequency_Fixed=32.768kHz, Manufacturer="Micro Crystal AG"
ZZ1: library part AssemblyNoteLabel
ZZ2 ZZ3 ZZ4 ZZ5 ZZ6 ZZ7 ZZ8 ZZ9: library part AssemblyNote

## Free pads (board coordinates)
  round 26 hole 12: 2(2090,2225) 3(2015,2025) 4(2070,1990) 5(215,1740) 5(1292.01,1513.94) 6(940,1025) 6(940,1085) 6(1540,2095) 6(2070,1855)
  round 60 hole 30: 7(1780,2635) 8(1910,2510) 9(2085,2510) 10(1370,2315) 11(1270,2245) 12(1335,2095) 13(1470,1980) 14(1350,1950) 15(920,1860) 16(985,1775) 17(930,1695) 18(780,1905) 19(475,2680) 20(245,2495) 21(105,2360) 22(105,2235) 23(310,515) 24(355,405) 26(1540,240) 27(1720,520) 28(2000,500) 29(1625,1210) 30(1595,1070) 31(2005,1750) 32(1890,1675) 33(1460,845)

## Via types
v1: diameter 26, hole 12, Top Layer to Bottom Layer, 30 vias
v2: diameter 19.68, hole 7.87, Top Layer to Bottom Layer, 16 vias
v3: diameter 34, hole 16, Top Layer to Bottom Layer, 6 vias

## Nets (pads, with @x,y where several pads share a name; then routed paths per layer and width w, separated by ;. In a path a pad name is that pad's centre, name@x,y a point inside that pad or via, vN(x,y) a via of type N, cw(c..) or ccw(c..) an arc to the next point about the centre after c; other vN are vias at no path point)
3V3: C5.1 C6.1 C7.1 J3.2 J11.1 J13.2 R11.1 R12.2 S1.2 S2.2 U2.37 U2.48 | length 6356.4
  Top Layer w8: C6.1@1044.88,1026.26 U2.37@1044.88,1116.81 ; U2.48@1261.42,1116.81 1287.01,1116.81 1301.77,1102.05 C7.1@1301.77,1065.67
  Top Layer w15: v1(560.35,590) R12.2@602.41,590 ; v3(1043.62,991.38) C6.1@1043.62,1025 ; C7.1@1301.77,1065.67 v3(1370,997.44) ; R11.1@1540,2338.62 1659.61,2338.62 S2.2@1663.9,2334.33
  Top Layer w40: S2.2@1659.61,2338.62 1665,2344.02 v3(1665,2440) ; S1.2@1663.9,2134.33 S2.2@1663.9,2334.33
  Bottom Layer w15: 1043.62,900 v3(1043.62,991.38)
  Bottom Layer w20: 560.35,900 1043.62,900 1370,900 v3(1370,997.44)
  Bottom Layer w40: J11.1@200,1550 560.35,1550 ; J13.2@504.38,300 560.35,355.97 v1(560.35,590) 560.35,900 560.35,1550 ; v3(1665,2440) 1665,2770 1600,2835 600,2835 600,2500 870,2230 J3.2@870,2175 865.62,2175 805.62,2115 805.62,2045.62 560.35,1800.35 560.35,1550
\FAULT: J12.9 R2.1 U1.2 U2.10 | length 1989.3
  Top Layer w8: R2.1@1081.14,1930.67 1083.46,1932.99 U1.2@1083.46,1975.06 ; U2.10@1287.01,1319.57 1319.74,1319.57 v1(1324.93,1324.76)
  Top Layer w15: v1(1079.06,1851.06) 1081.14,1853.14 R2.1@1081.14,1930.67 ; v1(1194.22,1850) 1325,1850 1379.57,1795.43 1379.57,1329.57 v1(1381.68,1329.57)
  Bottom Layer w15: v1@1079.06,1850.94 v1(1079.06,1851.06) 1193.16,1851.06 v1(1194.22,1850) ; v1(1324.93,1324.76) 1329.74,1329.57 v1(1381.68,1329.57) ; v1@1379.57,1319.57 1379.57,1120.43 1750,750 J12.9@2000,750
A0RX: J14.14 J15.3 U2.25 | length 1828.9
  Top Layer w8: v1(699.16,1195.84) 699.16,743.46 782.63,660 1140,660 J15.3@1200,600 ; v1(699.16,1365.84) 844.16,1365.84 851.06,1358.94 U2.25@1019.29,1358.94
  Top Layer w15: J15.3@1200,600 1251.16,548.84 1320.23,548.84 1348.84,520.23 1348.84,451.16 J14.14@1400,400
  Bottom Layer w8: v1(699.16,1195.84) v1(699.16,1365.84)
A0TX: J14.12 J15.2 U2.24 | length 1883.6
  Top Layer w8: v1@665.47,1384.53 665.94,1385 v1(670,1385) 675.71,1390.71 1044.88,1390.71 U2.24@1044.88,1384.53 ; v1(670,1220) 670,750 725.13,694.87 725.3,694.87 870.18,550 1100,550 ; J15.2@1100,600 1100,550 ; J14.12@1300,400 1245.34,454.66 1175.34,454.66 1150,480 1150,520 1120,550 1100,550
  Bottom Layer w8: v1@665,1215 v1(670,1220) v1(670,1385) v1@665,1385
A1RX: J11.3 U1.3 U2.21 | length 1548.6
  Top Layer w8: J11.3@200,1350 205.13,1355.13 500.2,1355.13 609.82,1464.75 1099.19,1464.75 1103.94,1460 ; U1.3@1103.15,1975.06 1103.94,1974.27 1103.94,1545.68 1098.75,1540.49 1098.75,1514.7 1103.94,1509.51 1103.94,1460 ; U2.21@1103.94,1384.53 1103.94,1460
A1TX: J11.4 U1.4 U2.20 | length 1837.8
  Top Layer w8: U2.20@1122.83,1385.32 U2.20@1123.62,1384.53 v1(1123.62,1525) 1123.62,1776.38 1122.83,1777.17 U1.4@1122.83,1975.06
  Top Layer w15: J11.4@200,1250 145,1305 145,1472.84 172.16,1500 280,1500 305,1525 v3(1030,1525)
  Bottom Layer w15: v3(1030,1525) v1(1123.62,1525)
A10_ADCIN: C8.1 J11.2 R6.1 U2.18 | length 1206.3
  Top Layer w8: U2.18@1162.99,1384.53 1162.99,1437.99 v1(1175,1450)
  Top Layer w15: J11.2@200,1450 305,1450 344.06,1489.06 v1@1079.06,1489.06
  Top Layer w20: v1@1079.06,1489.06 v1(1079.06,1489.62) ; v1(1175,1450) C8.1@1228.5,1450 1228.5,1517.01 R6.1@1230,1518.5
  Bottom Layer w20: v1(1079.06,1489.62) 1079.06,1480.94 1110,1450 v1(1175,1450)
BTN1: S2.1 U2.34 | length 3758.2
  Top Layer w8: U2.34@1019.29,1181.77 770.84,1181.77 770.84,739.14 798.23,711.75 1726.75,711.75 1956.63,941.63 1956.63,1067.96 1982.04,1093.37 2038.37,1093.37 2120,1175 2120,2380 2100,2400 1985.47,2400 S2.1@1919.8,2334.33
BTN2: S1.1 U2.2 | length 1345.9
  Top Layer w8: U2.2@1287.01,1162.09 1436.19,1162.09 1436.19,1153.81 v1(1440,1150)
  Top Layer w15: v1(1480,1400) 1480,1694.53 S1.1@1919.8,2134.33
  Bottom Layer w15: v1(1440,1150) 1440,1360 v1(1480,1400)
